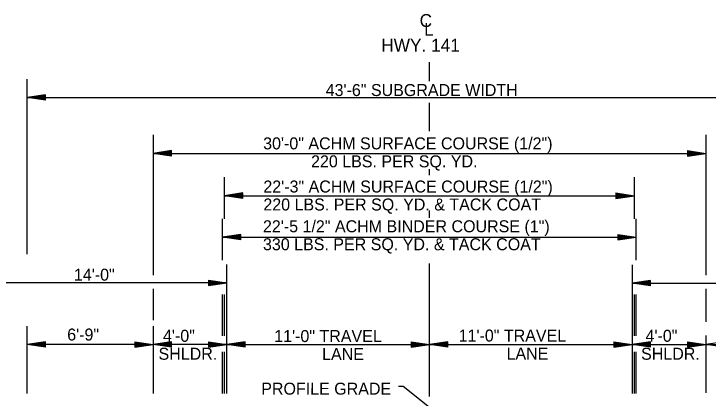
# Model space of a CAD drawing. Extents: x 6848689 to 6848907, y 1900908 to 1901005.
# Drawn here: x 6848723.54 to 6848761.22, y 1900983.14 to 1901003.99 of the extents above; entities that cross this region are included whole.
import ezdxf

# ---------------------------------------------------------------- set-up
doc = ezdxf.new("R2010")
doc.units = 0
for name, color, linetype in [('Default', 7, 'Continuous'), ('R_Draft', 7, 'Continuous'), ('R_No Plot', 7, 'Continuous')]:
    doc.layers.add(name, color=color, linetype=linetype)

msp = doc.modelspace()

# ---------------------------------------------------------------- linework, layer by layer
at = {"layer": 'Default'}
msp.add_line((6848735.099, 1900986.043), (6848757.099, 1900986.043), dxfattribs=at)
at = {"layer": 'R_Draft'}
for p, q in [((6848725.258, 1900999.597), (6848724.258, 1900999.447)), ((6848725.258, 1900999.297), (6848724.258, 1900999.447)), ((6848725.258, 1900999.572), (6848724.425, 1900999.447)), ((6848725.258, 1900999.322), (6848724.425, 1900999.447)), ((6848725.258, 1900999.547), (6848724.597, 1900999.447)), ((6848725.258, 1900999.348), (6848724.597, 1900999.447)), ((6848725.258, 1900999.522), (6848724.764, 1900999.447)), ((6848725.258, 1900999.373), (6848724.764, 1900999.447)), ((6848725.258, 1900999.496), (6848724.933, 1900999.447)), ((6848725.258, 1900999.399), (6848724.933, 1900999.447)), ((6848725.258, 1900999.471), (6848725.1, 1900999.447)), ((6848725.258, 1900999.424), (6848725.1, 1900999.447)), ((6848725.258, 1900999.297), (6848725.258, 1900999.597)), ((6848732.099, 1900996.565), (6848731.099, 1900996.415)), ((6848732.099, 1900996.265), (6848731.099, 1900996.415)), ((6848732.099, 1900996.54), (6848731.266, 1900996.415)), ((6848732.099, 1900996.29), (6848731.266, 1900996.415)), ((6848732.099, 1900996.514), (6848731.438, 1900996.415)), ((6848732.099, 1900996.315), (6848731.438, 1900996.415)), ((6848732.099, 1900996.489), (6848731.605, 1900996.415)), ((6848732.099, 1900996.34), (6848731.605, 1900996.415)), ((6848732.099, 1900996.464), (6848731.774, 1900996.415)), ((6848732.099, 1900996.366), (6848731.774, 1900996.415)), ((6848732.099, 1900996.438), (6848731.941, 1900996.415)), ((6848732.099, 1900996.391), (6848731.941, 1900996.415)), ((6848732.099, 1900996.265), (6848732.099, 1900996.565)), ((6848760.096, 1900996.565), (6848761.096, 1900996.415)), ((6848760.096, 1900996.565), (6848760.096, 1900996.265)), ((6848760.096, 1900996.54), (6848760.929, 1900996.415)), ((6848760.096, 1900996.514), (6848760.757, 1900996.415)), ((6848760.096, 1900996.489), (6848760.59, 1900996.415)), ((6848760.096, 1900996.463), (6848760.421, 1900996.415)), ((6848760.096, 1900996.438), (6848760.254, 1900996.415)), ((6848760.096, 1900996.265), (6848761.096, 1900996.415)), ((6848760.096, 1900996.366), (6848760.421, 1900996.415)), ((6848760.096, 1900996.315), (6848760.757, 1900996.415)), ((6848760.096, 1900996.29), (6848760.929, 1900996.415)), ((6848760.096, 1900996.34), (6848760.59, 1900996.415)), ((6848760.096, 1900996.391), (6848760.254, 1900996.415)), ((6848735.972, 1900994.271), (6848734.972, 1900994.121)), ((6848735.972, 1900993.971), (6848734.972, 1900994.121)), ((6848735.972, 1900994.246), (6848735.139, 1900994.121)), ((6848735.972, 1900993.996), (6848735.139, 1900994.121)), ((6848735.972, 1900994.221), (6848735.311, 1900994.121)), ((6848735.972, 1900994.022), (6848735.311, 1900994.121)), ((6848735.972, 1900994.196), (6848735.478, 1900994.121)), ((6848735.972, 1900994.047), (6848735.478, 1900994.121)), ((6848735.972, 1900994.17), (6848735.647, 1900994.121)), ((6848735.972, 1900994.073), (6848735.647, 1900994.121)), ((6848735.972, 1900994.145), (6848735.814, 1900994.121)), ((6848735.972, 1900994.098), (6848735.814, 1900994.121)), ((6848735.972, 1900993.971), (6848735.972, 1900994.271)), ((6848756.222, 1900994.271), (6848757.222, 1900994.121)), ((6848756.222, 1900994.271), (6848756.222, 1900993.971)), ((6848756.222, 1900994.246), (6848757.055, 1900994.121)), ((6848756.222, 1900994.221), (6848756.883, 1900994.121)), ((6848756.222, 1900994.196), (6848756.717, 1900994.121)), ((6848756.222, 1900994.17), (6848756.547, 1900994.121)), ((6848756.222, 1900994.145), (6848756.38, 1900994.121)), ((6848756.222, 1900993.971), (6848757.222, 1900994.121)), ((6848756.222, 1900994.072), (6848756.547, 1900994.121)), ((6848756.222, 1900994.022), (6848756.883, 1900994.121)), ((6848756.222, 1900993.996), (6848757.055, 1900994.121)), ((6848756.222, 1900994.047), (6848756.717, 1900994.121)), ((6848756.222, 1900994.098), (6848756.38, 1900994.121)), ((6848735.867, 1900992.021), (6848734.867, 1900991.871)), ((6848735.867, 1900991.721), (6848734.867, 1900991.871)), ((6848735.867, 1900991.996), (6848735.034, 1900991.871)), ((6848735.867, 1900991.746), (6848735.034, 1900991.871)), ((6848735.867, 1900991.97), (6848735.206, 1900991.871)), ((6848735.867, 1900991.771), (6848735.206, 1900991.871)), ((6848735.867, 1900991.945), (6848735.373, 1900991.871)), ((6848735.867, 1900991.796), (6848735.373, 1900991.871)), ((6848735.867, 1900991.92), (6848735.542, 1900991.871)), ((6848735.867, 1900991.822), (6848735.542, 1900991.871)), ((6848735.867, 1900991.894), (6848735.709, 1900991.871)), ((6848735.867, 1900991.847), (6848735.709, 1900991.871)), ((6848735.867, 1900991.721), (6848735.867, 1900992.021)), ((6848756.327, 1900992.021), (6848757.327, 1900991.871)), ((6848756.327, 1900992.021), (6848756.327, 1900991.721)), ((6848756.327, 1900991.996), (6848757.16, 1900991.871)), ((6848756.327, 1900991.97), (6848756.988, 1900991.871)), ((6848756.327, 1900991.945), (6848756.822, 1900991.871)), ((6848756.327, 1900991.919), (6848756.652, 1900991.871)), ((6848756.327, 1900991.894), (6848756.485, 1900991.871)), ((6848756.327, 1900991.721), (6848757.327, 1900991.871)), ((6848756.327, 1900991.822), (6848756.652, 1900991.871)), ((6848756.327, 1900991.771), (6848756.988, 1900991.871)), ((6848756.327, 1900991.746), (6848757.16, 1900991.871)), ((6848756.327, 1900991.796), (6848756.822, 1900991.871)), ((6848756.327, 1900991.847), (6848756.485, 1900991.871)), ((6848734.099, 1900989.546), (6848735.099, 1900989.396)), ((6848734.099, 1900989.546), (6848734.099, 1900989.246)), ((6848734.099, 1900989.521), (6848734.932, 1900989.396)), ((6848734.099, 1900989.496), (6848734.76, 1900989.396)), ((6848734.099, 1900989.471), (6848734.594, 1900989.396)), ((6848734.099, 1900989.445), (6848734.424, 1900989.396)), ((6848734.099, 1900989.42), (6848734.257, 1900989.396)), ((6848734.099, 1900989.246), (6848735.099, 1900989.396)), ((6848734.099, 1900989.347), (6848734.424, 1900989.396)), ((6848734.099, 1900989.297), (6848734.76, 1900989.396)), ((6848734.099, 1900989.271), (6848734.932, 1900989.396)), ((6848734.099, 1900989.322), (6848734.594, 1900989.396)), ((6848734.099, 1900989.373), (6848734.257, 1900989.396)), ((6848758.103, 1900989.525), (6848757.103, 1900989.375)), ((6848758.103, 1900989.225), (6848757.103, 1900989.375)), ((6848758.103, 1900989.5), (6848757.27, 1900989.375)), ((6848758.103, 1900989.25), (6848757.27, 1900989.375)), ((6848758.103, 1900989.475), (6848757.442, 1900989.375)), ((6848758.103, 1900989.276), (6848757.442, 1900989.375)), ((6848758.103, 1900989.45), (6848757.609, 1900989.375)), ((6848758.103, 1900989.301), (6848757.609, 1900989.375)), ((6848758.103, 1900989.424), (6848757.778, 1900989.375)), ((6848758.103, 1900989.327), (6848757.778, 1900989.375)), ((6848758.103, 1900989.399), (6848757.945, 1900989.375)), ((6848758.103, 1900989.352), (6848757.945, 1900989.375)), ((6848758.103, 1900989.225), (6848758.103, 1900989.525)), ((6848725.259, 1900986.193), (6848724.259, 1900986.043)), ((6848725.259, 1900985.893), (6848725.259, 1900986.193)), ((6848730.099, 1900986.193), (6848731.099, 1900986.043)), ((6848730.099, 1900986.193), (6848730.099, 1900985.893)), ((6848732.099, 1900986.193), (6848731.099, 1900986.043)), ((6848732.099, 1900985.893), (6848732.099, 1900986.193)), ((6848734.099, 1900986.193), (6848735.099, 1900986.043)), ((6848734.099, 1900986.193), (6848734.099, 1900985.893)), ((6848736.099, 1900986.193), (6848735.099, 1900986.043)), ((6848736.099, 1900985.893), (6848736.099, 1900986.193)), ((6848745.099, 1900986.193), (6848746.099, 1900986.043)), ((6848745.099, 1900986.193), (6848745.099, 1900985.893)), ((6848747.099, 1900986.193), (6848746.099, 1900986.043)), ((6848747.099, 1900985.893), (6848747.099, 1900986.193)), ((6848756.1, 1900986.193), (6848757.1, 1900986.043)), ((6848756.1, 1900986.193), (6848756.1, 1900985.893)), ((6848758.1, 1900986.193), (6848757.1, 1900986.043)), ((6848758.1, 1900985.893), (6848758.1, 1900986.193)), ((6848760.1, 1900986.193), (6848761.1, 1900986.043)), ((6848760.1, 1900986.193), (6848760.1, 1900985.893)), ((6848762.1, 1900986.193), (6848761.1, 1900986.043)), ((6848725.259, 1900985.893), (6848724.259, 1900986.043)), ((6848725.259, 1900986.168), (6848724.426, 1900986.043)), ((6848725.259, 1900985.918), (6848724.426, 1900986.043)), ((6848725.259, 1900986.142), (6848724.598, 1900986.043)), ((6848725.259, 1900985.943), (6848724.598, 1900986.043)), ((6848725.259, 1900986.117), (6848724.764, 1900986.043)), ((6848725.259, 1900985.968), (6848724.764, 1900986.043)), ((6848725.259, 1900986.092), (6848724.934, 1900986.043)), ((6848725.259, 1900985.994), (6848724.934, 1900986.043)), ((6848725.259, 1900986.066), (6848725.101, 1900986.043)), ((6848725.259, 1900986.019), (6848725.101, 1900986.043)), ((6848730.099, 1900986.168), (6848730.932, 1900986.043)), ((6848730.099, 1900986.142), (6848730.76, 1900986.043)), ((6848730.099, 1900986.117), (6848730.594, 1900986.043)), ((6848730.099, 1900986.091), (6848730.424, 1900986.043)), ((6848730.099, 1900986.066), (6848730.257, 1900986.043)), ((6848730.099, 1900985.893), (6848731.099, 1900986.043)), ((6848730.099, 1900985.994), (6848730.424, 1900986.043)), ((6848730.099, 1900985.943), (6848730.76, 1900986.043)), ((6848730.099, 1900985.918), (6848730.932, 1900986.043)), ((6848730.099, 1900985.968), (6848730.594, 1900986.043)), ((6848730.099, 1900986.019), (6848730.257, 1900986.043)), ((6848732.099, 1900985.893), (6848731.099, 1900986.043)), ((6848732.099, 1900986.168), (6848731.266, 1900986.043)), ((6848732.099, 1900985.918), (6848731.266, 1900986.043)), ((6848732.099, 1900986.142), (6848731.438, 1900986.043)), ((6848732.099, 1900985.943), (6848731.438, 1900986.043)), ((6848732.099, 1900986.117), (6848731.605, 1900986.043)), ((6848732.099, 1900985.968), (6848731.605, 1900986.043)), ((6848732.099, 1900986.092), (6848731.774, 1900986.043)), ((6848732.099, 1900985.994), (6848731.774, 1900986.043)), ((6848732.099, 1900986.066), (6848731.941, 1900986.043)), ((6848732.099, 1900986.019), (6848731.941, 1900986.043)), ((6848734.099, 1900986.168), (6848734.932, 1900986.043)), ((6848734.099, 1900986.142), (6848734.76, 1900986.043)), ((6848734.099, 1900986.117), (6848734.594, 1900986.043)), ((6848734.099, 1900986.091), (6848734.424, 1900986.043)), ((6848734.099, 1900986.066), (6848734.257, 1900986.043)), ((6848734.099, 1900985.893), (6848735.099, 1900986.043)), ((6848734.099, 1900985.994), (6848734.424, 1900986.043)), ((6848734.099, 1900985.943), (6848734.76, 1900986.043)), ((6848734.099, 1900985.918), (6848734.932, 1900986.043)), ((6848734.099, 1900985.968), (6848734.594, 1900986.043)), ((6848734.099, 1900986.019), (6848734.257, 1900986.043)), ((6848736.099, 1900985.893), (6848735.099, 1900986.043)), ((6848736.099, 1900986.168), (6848735.266, 1900986.043)), ((6848736.099, 1900985.918), (6848735.266, 1900986.043)), ((6848736.099, 1900986.142), (6848735.438, 1900986.043)), ((6848736.099, 1900985.943), (6848735.438, 1900986.043)), ((6848736.099, 1900986.117), (6848735.605, 1900986.043)), ((6848736.099, 1900985.968), (6848735.605, 1900986.043)), ((6848736.099, 1900986.092), (6848735.774, 1900986.043)), ((6848736.099, 1900985.994), (6848735.774, 1900986.043)), ((6848736.099, 1900986.066), (6848735.941, 1900986.043)), ((6848736.099, 1900986.019), (6848735.941, 1900986.043)), ((6848745.099, 1900986.168), (6848745.932, 1900986.043)), ((6848745.099, 1900986.142), (6848745.76, 1900986.043)), ((6848745.099, 1900986.117), (6848745.594, 1900986.043)), ((6848745.099, 1900986.091), (6848745.424, 1900986.043)), ((6848745.099, 1900986.066), (6848745.257, 1900986.043)), ((6848745.099, 1900985.893), (6848746.099, 1900986.043)), ((6848745.099, 1900985.994), (6848745.424, 1900986.043)), ((6848745.099, 1900985.943), (6848745.76, 1900986.043)), ((6848745.099, 1900985.918), (6848745.932, 1900986.043)), ((6848745.099, 1900985.968), (6848745.594, 1900986.043)), ((6848745.099, 1900986.019), (6848745.257, 1900986.043)), ((6848747.099, 1900985.893), (6848746.099, 1900986.043)), ((6848747.099, 1900986.168), (6848746.266, 1900986.043)), ((6848747.099, 1900985.918), (6848746.266, 1900986.043)), ((6848747.099, 1900986.142), (6848746.438, 1900986.043)), ((6848747.099, 1900985.943), (6848746.438, 1900986.043)), ((6848747.099, 1900986.117), (6848746.605, 1900986.043)), ((6848747.099, 1900985.968), (6848746.605, 1900986.043)), ((6848747.099, 1900986.092), (6848746.774, 1900986.043)), ((6848747.099, 1900985.994), (6848746.774, 1900986.043)), ((6848747.099, 1900986.066), (6848746.941, 1900986.043)), ((6848747.099, 1900986.019), (6848746.941, 1900986.043)), ((6848756.1, 1900986.168), (6848756.933, 1900986.043)), ((6848756.1, 1900986.142), (6848756.761, 1900986.043)), ((6848756.1, 1900986.117), (6848756.594, 1900986.043)), ((6848756.1, 1900986.091), (6848756.425, 1900986.043)), ((6848756.1, 1900986.066), (6848756.258, 1900986.043)), ((6848756.1, 1900985.893), (6848757.1, 1900986.043)), ((6848756.1, 1900985.994), (6848756.425, 1900986.043)), ((6848756.1, 1900985.943), (6848756.761, 1900986.043)), ((6848756.1, 1900985.918), (6848756.933, 1900986.043)), ((6848756.1, 1900985.968), (6848756.594, 1900986.043)), ((6848756.1, 1900986.019), (6848756.258, 1900986.043)), ((6848758.1, 1900985.893), (6848757.1, 1900986.043)), ((6848758.1, 1900986.168), (6848757.267, 1900986.043)), ((6848758.1, 1900985.918), (6848757.267, 1900986.043)), ((6848758.1, 1900986.142), (6848757.439, 1900986.043)), ((6848758.1, 1900985.943), (6848757.439, 1900986.043)), ((6848758.1, 1900986.117), (6848757.605, 1900986.043)), ((6848758.1, 1900985.968), (6848757.605, 1900986.043)), ((6848758.1, 1900986.092), (6848757.775, 1900986.043)), ((6848758.1, 1900985.994), (6848757.775, 1900986.043)), ((6848758.1, 1900986.066), (6848757.942, 1900986.043)), ((6848758.1, 1900986.019), (6848757.942, 1900986.043)), ((6848760.1, 1900986.168), (6848760.933, 1900986.043)), ((6848760.1, 1900986.142), (6848760.761, 1900986.043)), ((6848760.1, 1900986.117), (6848760.594, 1900986.043)), ((6848760.1, 1900986.091), (6848760.425, 1900986.043)), ((6848760.1, 1900986.066), (6848760.258, 1900986.043)), ((6848760.1, 1900985.893), (6848761.1, 1900986.043)), ((6848760.1, 1900985.994), (6848760.425, 1900986.043)), ((6848760.1, 1900985.943), (6848760.761, 1900986.043)), ((6848760.1, 1900985.918), (6848760.933, 1900986.043)), ((6848760.1, 1900985.968), (6848760.594, 1900986.043)), ((6848760.1, 1900986.019), (6848760.258, 1900986.043)), ((6848762.1, 1900985.893), (6848761.1, 1900986.043))]:
    msp.add_line(p, q, dxfattribs=at)
msp.add_lwpolyline([(6848746.097, 1900982.626), (6848744.67, 1900983.771), (6848744.426, 1900983.774)], dxfattribs=at)
at = {"layer": 'R_No Plot'}
for p, q in [((6848746.097, 1901000.335), (6848746.097, 1901001.364)), ((6848724.258, 1900990.947), (6848724.258, 1901000.447)), ((6848724.258, 1900999.447), (6848767.936, 1900999.447)), ((6848746.097, 1900997.619), (6848746.097, 1900999.162)), ((6848731.099, 1900997.415), (6848731.099, 1900989.806)), ((6848761.096, 1900997.415), (6848761.096, 1900989.806)), ((6848731.099, 1900996.415), (6848761.096, 1900996.415)), ((6848746.097, 1900995.232), (6848746.097, 1900995.564)), ((6848734.972, 1900992.868), (6848734.972, 1900995.121)), ((6848757.222, 1900992.868), (6848757.222, 1900995.121)), ((6848734.972, 1900994.121), (6848757.222, 1900994.121)), ((6848746.097, 1900992.925), (6848746.097, 1900993.309)), ((6848734.867, 1900990.617), (6848734.867, 1900992.871)), ((6848757.327, 1900990.617), (6848757.327, 1900992.871)), ((6848734.867, 1900991.871), (6848757.327, 1900991.871)), ((6848735.099, 1900986.043), (6848735.099, 1900990.396)), ((6848746.097, 1900983.222), (6848746.097, 1900990.449)), ((6848757.104, 1900990.375), (6848757.097, 1900983.395)), ((6848735.099, 1900989.396), (6848721.099, 1900989.396)), ((6848757.103, 1900989.375), (6848771.103, 1900989.375)), ((6848731.099, 1900989.07), (6848731.099, 1900987.366)), ((6848761.096, 1900989.07), (6848761.096, 1900987.281)), ((6848734.867, 1900986.512), (6848734.867, 1900988.766)), ((6848734.972, 1900986.512), (6848734.972, 1900988.766)), ((6848757.222, 1900986.512), (6848757.222, 1900988.766)), ((6848757.327, 1900986.512), (6848757.327, 1900988.766)), ((6848724.258, 1900983.39), (6848724.258, 1900987.038)), ((6848731.099, 1900987.043), (6848731.099, 1900983.395)), ((6848735.099, 1900983.395), (6848735.099, 1900986.27)), ((6848761.1, 1900986.543), (6848761.1, 1900983.422)), ((6848730.974, 1900986.043), (6848724.259, 1900986.043)), ((6848735.099, 1900986.043), (6848731.099, 1900986.043)), ((6848757.1, 1900986.043), (6848761.1, 1900986.043)), ((6848761.1, 1900986.043), (6848767.936, 1900986.043)), ((6848734.867, 1900983.395), (6848734.867, 1900985.648)), ((6848734.972, 1900983.395), (6848734.972, 1900985.648)), ((6848757.222, 1900983.395), (6848757.222, 1900985.648)), ((6848757.327, 1900983.395), (6848757.327, 1900985.648))]:
    msp.add_line(p, q, dxfattribs=at)

# ---------------------------------------------------------------- texts
at = {"layer": 'R_Draft'}
for s, height, p in [('C', 0.7, (6848745.564, 1901003.276)), ('L', 0.7, (6848745.81, 1901002.799)), ('HWY. 141', 0.7, (6848743.483, 1901001.935)), ('43\'-6" SUBGRADE WIDTH', 0.65, (6848740.467, 1900999.529)), ('30\'-0" ACHM SURFACE COURSE (1/2")', 0.65, (6848737.072, 1900996.635)), ('220 LBS. PER SQ. YD. ', 0.65, (6848739.672, 1900995.66)), ('22\'-3" ACHM SURFACE COURSE (1/2")', 0.65, (6848737.084, 1900994.294)), ('220 LBS. PER SQ. YD. & TACK COAT', 0.65, (6848737.084, 1900993.319)), ('22\'-5 1/2" ACHM BINDER COURSE (1")', 0.65, (6848737.063, 1900992.136)), ('330 LBS. PER SQ. YD. & TACK COAT', 0.65, (6848737.063, 1900991.161)), ('14\'-0"', 0.65, (6848726.802, 1900989.51)), ('6\'-9"', 0.65, (6848726.437, 1900986.262)), (' 4\'-0"', 0.65, (6848731.395, 1900986.195)), ('11\'-0" TRAVEL ', 0.65, (6848737.673, 1900986.179)), ('11\'-0" TRAVEL ', 0.65, (6848747.682, 1900986.207)), (' 4\'-0"', 0.65, (6848757.585, 1900986.195)), ('SHLDR.', 0.65, (6848731.395, 1900985.22)), ('LANE', 0.65, (6848740.273, 1900985.204)), ('LANE', 0.65, (6848750.282, 1900985.232)), ('SHLDR.', 0.65, (6848757.585, 1900985.22))]:
    msp.add_text(s, height=height, dxfattribs=at).set_placement(p)
msp.add_text('PROFILE GRADE', height=0.65, rotation=359.98, dxfattribs=at).set_placement((6848736.969, 1900983.326))

doc.saveas('drawing.dxf')
